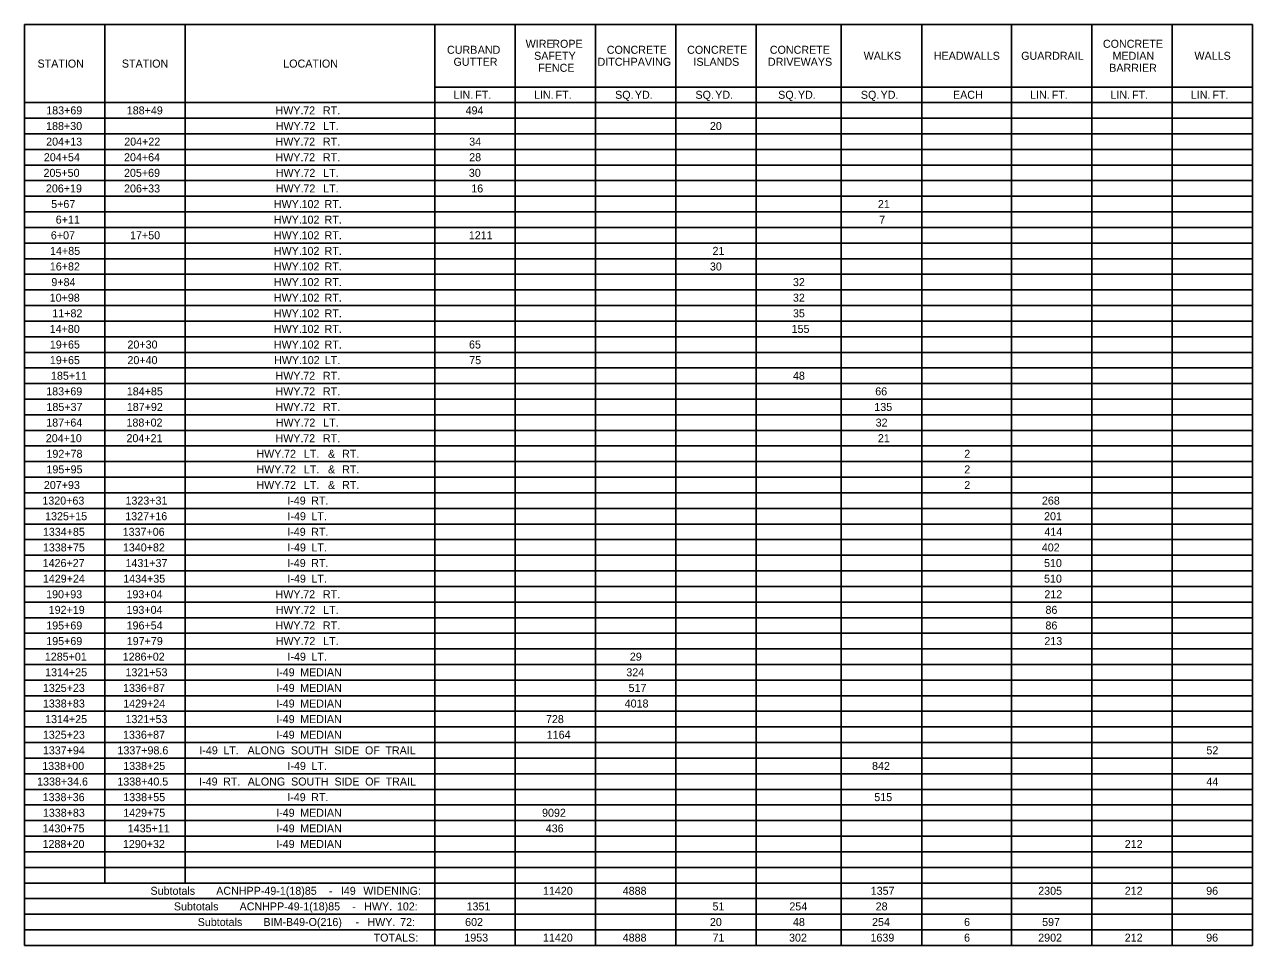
# Model space of a CAD drawing. Extents: x 1226657 to 1228145, y 151309 to 152305.
# Drawn here: x 1226657 to 1227424, y 151359 to 151934 of the extents above; entities that cross this region are included whole.
import ezdxf

# ---------------------------------------------------------------- set-up
doc = ezdxf.new("R2010")
doc.units = 0
doc.layers.add('R_Dimension', color=7, linetype='Continuous')

msp = doc.modelspace()

# ---------------------------------------------------------------- linework, layer by layer
at = {"layer": 'R_Dimension'}
for p, q in [((1226656.54, 151934.12), (1227423.86, 151934.12)), ((1226656.54, 151358.87), (1226656.54, 151934.12)), ((1226706.75, 151397.87), (1226706.75, 151934.12)), ((1226756.96, 151397.87), (1226756.96, 151934.12)), ((1226912.96, 151358.87), (1226912.96, 151934.12)), ((1226963.18, 151358.87), (1226963.18, 151934.12)), ((1227013.39, 151358.87), (1227013.39, 151934.12)), ((1227063.6, 151358.87), (1227063.6, 151934.12)), ((1227113.81, 151358.87), (1227113.81, 151934.12)), ((1227166.95, 151358.87), (1227166.95, 151934.12)), ((1227217.16, 151358.87), (1227217.16, 151934.12)), ((1227273.23, 151358.87), (1227273.23, 151934.12)), ((1227323.44, 151358.87), (1227323.44, 151934.12)), ((1227373.65, 151358.87), (1227373.65, 151934.12)), ((1227423.86, 151358.87), (1227423.86, 151934.12)), ((1226912.96, 151895.12), (1227423.86, 151895.12)), ((1226656.54, 151885.37), (1227423.86, 151885.37)), ((1226656.54, 151875.62), (1227423.86, 151875.62)), ((1226656.54, 151865.87), (1227423.86, 151865.87)), ((1226656.54, 151856.12), (1227423.86, 151856.12)), ((1226656.54, 151846.37), (1227423.86, 151846.37)), ((1226656.54, 151836.62), (1227423.86, 151836.62)), ((1226656.54, 151826.87), (1227423.86, 151826.87)), ((1226656.54, 151817.12), (1227423.86, 151817.12)), ((1226656.54, 151807.37), (1227423.86, 151807.37)), ((1226656.54, 151797.62), (1227423.86, 151797.62)), ((1226656.54, 151787.87), (1227423.86, 151787.87)), ((1226656.54, 151778.12), (1227423.86, 151778.12)), ((1226656.54, 151768.37), (1227423.86, 151768.37)), ((1226656.54, 151758.62), (1227423.86, 151758.62)), ((1226656.54, 151748.87), (1227423.86, 151748.87)), ((1226656.54, 151739.12), (1227423.86, 151739.12)), ((1226656.54, 151729.37), (1227423.86, 151729.37)), ((1226656.54, 151719.62), (1227423.86, 151719.62)), ((1226656.54, 151709.87), (1227423.86, 151709.87)), ((1226656.54, 151700.12), (1227423.86, 151700.12)), ((1226656.54, 151690.37), (1227423.86, 151690.37)), ((1226656.54, 151680.62), (1227423.86, 151680.62)), ((1226656.54, 151670.87), (1227423.86, 151670.87)), ((1226656.54, 151661.12), (1227423.86, 151661.12)), ((1226656.54, 151651.37), (1227423.86, 151651.37)), ((1226656.54, 151641.62), (1227423.86, 151641.62)), ((1226656.54, 151631.87), (1227423.86, 151631.87)), ((1226656.54, 151622.12), (1227423.86, 151622.12)), ((1226656.54, 151612.37), (1227423.86, 151612.37)), ((1226656.54, 151602.62), (1227423.86, 151602.62)), ((1226656.54, 151592.87), (1227423.86, 151592.87)), ((1226656.54, 151583.12), (1227423.86, 151583.12)), ((1226656.54, 151573.37), (1227423.86, 151573.37)), ((1226656.54, 151563.62), (1227423.86, 151563.62)), ((1226656.54, 151553.87), (1227423.86, 151553.87)), ((1226656.54, 151544.12), (1227423.86, 151544.12)), ((1226656.54, 151534.37), (1227423.86, 151534.37)), ((1226656.54, 151524.62), (1227423.86, 151524.62)), ((1226656.54, 151514.87), (1227423.86, 151514.87)), ((1226656.54, 151505.12), (1227423.86, 151505.12)), ((1226656.54, 151495.37), (1227423.86, 151495.37)), ((1226656.54, 151485.62), (1227423.86, 151485.62)), ((1226656.54, 151475.87), (1227423.86, 151475.87)), ((1226656.54, 151466.12), (1227423.86, 151466.12)), ((1226656.54, 151456.37), (1227423.86, 151456.37)), ((1226656.54, 151446.62), (1227423.86, 151446.62)), ((1226656.54, 151436.87), (1227423.86, 151436.87)), ((1226656.54, 151427.12), (1227423.86, 151427.12)), ((1226656.54, 151417.37), (1227423.86, 151417.37)), ((1226656.54, 151407.62), (1227423.86, 151407.62)), ((1226656.54, 151397.87), (1227423.86, 151397.87)), ((1226656.54, 151388.12), (1227423.86, 151388.12)), ((1226656.54, 151378.37), (1227423.86, 151378.37)), ((1226656.54, 151368.62), (1227423.86, 151368.62)), ((1226656.54, 151358.87), (1227423.86, 151358.87))]:
    msp.add_line(p, q, dxfattribs=at)

# ---------------------------------------------------------------- texts
for s, p in [('WIRE', (1226969.68, 151919.62)), (' ROPE', (1226984.48, 151919.62)), ('CONCRETE', (1227330.43, 151919.62)), ('CURB', (1226920.53, 151915.87)), (' AND', (1226937.89, 151915.87)), ('SAFETY', (1226974.97, 151912.12)), ('CONCRETE', (1227020.38, 151915.87)), ('CONCRETE', (1227070.6, 151915.87)), ('CONCRETE', (1227122.27, 151915.87)), ('WALKS', (1227180.92, 151912.12)), ('HEADWALLS', (1227224.76, 151912.12)), ('GUARDRAIL', (1227279.36, 151912.12)), ('MEDIAN', (1227336.44, 151912.12)), ('WALLS', (1227387.62, 151912.12)), ('STATION', (1226664.64, 151907.25)), ('STATION', (1226717.35, 151907.25)), ('LOCATION', (1226818.21, 151907.25)), ('GUTTER', (1226924.62, 151908.37)), ('FENCE', (1226977.53, 151904.62)), ('DITCH', (1227014.6, 151908.37)), (' PAVING', (1227033.42, 151908.37)), ('ISLANDS', (1227074.57, 151908.37)), ('DRIVEWAYS', (1227121.09, 151908.37)), ('BARRIER', (1227334.39, 151904.62)), ('LIN.', (1226924.66, 151887.75)), (' FT.', (1226936.32, 151887.75)), ('LIN.', (1226974.88, 151887.75)), (' FT.', (1226986.53, 151887.75)), ('SQ.', (1227025.6, 151887.75)), (' YD.', (1227036.07, 151887.75)), ('SQ.', (1227075.81, 151887.75)), (' YD.', (1227086.29, 151887.75)), ('SQ.', (1227127.49, 151887.75)), (' YD.', (1227137.96, 151887.75)), ('SQ.', (1227179.16, 151887.75)), (' YD.', (1227189.64, 151887.75)), ('EACH', (1227236.73, 151887.75)), ('LIN.', (1227284.93, 151887.75)), (' FT.', (1227296.58, 151887.75)), ('LIN.', (1227335.14, 151887.75)), (' FT.', (1227346.79, 151887.75)), ('LIN.', (1227385.35, 151887.75)), (' FT.', (1227397, 151887.75)), ('183+69', (1226670.09, 151878)), ('188+49', (1226720.42, 151878)), ('HWY.', (1226813.39, 151878)), (' 72', (1226828.82, 151878)), (' RT.', (1226841.14, 151878)), ('494', (1226932.16, 151878)), ('188+30', (1226670.01, 151868.25)), ('HWY.', (1226813.51, 151868.25)), (' 72', (1226828.94, 151868.25)), (' LT.', (1226841.26, 151868.25)), ('20', (1227084.83, 151868.25)), ('204+13', (1226670.03, 151858.5)), ('204+22', (1226718.83, 151858.5)), ('HWY.', (1226813.39, 151858.5)), (' 72', (1226828.82, 151858.5)), (' RT.', (1226841.14, 151858.5)), ('34', (1226934.41, 151858.5)), ('204+54', (1226668.61, 151848.75)), ('204+64', (1226718.71, 151848.75)), ('HWY.', (1226813.39, 151848.75)), (' 72', (1226828.82, 151848.75)), (' RT.', (1226841.14, 151848.75)), ('28', (1226934.41, 151848.75)), ('205+50', (1226668.4, 151839)), ('205+69', (1226718.69, 151839)), ('HWY.', (1226813.51, 151839)), (' 72', (1226828.94, 151839)), (' LT.', (1226841.26, 151839)), ('30', (1226934.19, 151839)), ('206+19', (1226669.89, 151829.25)), ('206+33', (1226718.71, 151829.25)), ('HWY.', (1226813.51, 151829.25)), (' 72', (1226828.94, 151829.25)), (' LT.', (1226841.26, 151829.25)), ('16', (1226935.69, 151829.25)), ('5+67', (1226673.18, 151819.5)), ('HWY.', (1226812.36, 151819.5)), (' 102', (1226827.8, 151819.5)), (' RT.', (1226842.17, 151819.5)), ('21', (1227189.81, 151819.5)), ('6+11', (1226676.01, 151809.75)), ('HWY.', (1226812.36, 151809.75)), (' 102', (1226827.8, 151809.75)), (' RT.', (1226842.17, 151809.75)), ('7', (1227190.64, 151809.75)), ('6+07', (1226672.98, 151800)), ('17+50', (1226722.47, 151800)), ('HWY.', (1226812.36, 151800)), (' 102', (1226827.8, 151800)), (' RT.', (1226842.17, 151800)), ('1211', (1226934.17, 151800)), ('14+85', (1226672.47, 151790.25)), ('HWY.', (1226812.36, 151790.25)), (' 102', (1226827.8, 151790.25)), (' RT.', (1226842.17, 151790.25)), ('21', (1227086.46, 151790.25)), ('16+82', (1226672.35, 151780.5)), ('HWY.', (1226812.36, 151780.5)), (' 102', (1226827.8, 151780.5)), (' RT.', (1226842.17, 151780.5)), ('30', (1227084.83, 151780.5)), ('9+84', (1226673.3, 151770.75)), ('HWY.', (1226812.36, 151770.75)), (' 102', (1226827.8, 151770.75)), (' RT.', (1226842.17, 151770.75)), ('32', (1227136.72, 151770.75)), ('10+98', (1226672.27, 151761)), ('HWY.', (1226812.36, 151761)), (' 102', (1226827.8, 151761)), (' RT.', (1226842.17, 151761)), ('32', (1227136.72, 151761)), ('11+82', (1226673.89, 151751.25)), ('HWY.', (1226812.36, 151751.25)), (' 102', (1226827.8, 151751.25)), (' RT.', (1226842.17, 151751.25)), ('35', (1227136.72, 151751.25)), ('14+80', (1226672.25, 151741.5)), ('HWY.', (1226812.36, 151741.5)), (' 102', (1226827.8, 151741.5)), (' RT.', (1226842.17, 151741.5)), ('155', (1227135.89, 151741.5)), ('19+65', (1226672.35, 151731.75)), ('20+30', (1226720.85, 151731.75)), ('HWY.', (1226812.36, 151731.75)), (' 102', (1226827.8, 151731.75)), (' RT.', (1226842.17, 151731.75)), ('65', (1226934.29, 151731.75)), ('19+65', (1226672.35, 151722)), ('20+40', (1226720.85, 151722)), ('HWY.', (1226812.48, 151722)), (' 102', (1226827.92, 151722)), (' LT.', (1226842.29, 151722)), ('75', (1226934.41, 151722)), ('185+11', (1226673.06, 151712.25)), ('HWY.', (1226813.39, 151712.25)), (' 72', (1226828.82, 151712.25)), (' RT.', (1226841.14, 151712.25)), ('48', (1227136.72, 151712.25)), ('183+69', (1226670.09, 151702.5)), ('184+85', (1226720.44, 151702.5)), ('HWY.', (1226813.39, 151702.5)), (' 72', (1226828.82, 151702.5)), (' RT.', (1226841.14, 151702.5)), ('66', (1227188.14, 151702.5)), ('185+37', (1226670.23, 151692.75)), ('187+92', (1226720.44, 151692.75)), ('HWY.', (1226813.39, 151692.75)), (' 72', (1226828.82, 151692.75)), (' RT.', (1226841.14, 151692.75)), ('135', (1227187.57, 151692.75)), ('187+64', (1226670.11, 151683)), ('188+02', (1226720.24, 151683)), ('HWY.', (1226813.51, 151683)), (' 72', (1226828.94, 151683)), (' LT.', (1226841.26, 151683)), ('32', (1227188.4, 151683)), ('204+10', (1226669.81, 151673.25)), ('204+21', (1226720.24, 151673.25)), ('HWY.', (1226813.39, 151673.25)), (' 72', (1226828.82, 151673.25)), (' RT.', (1226841.14, 151673.25)), ('21', (1227189.81, 151673.25)), ('192+78', (1226670.23, 151663.5)), ('HWY.', (1226801.42, 151663.5)), (' 72', (1226816.85, 151663.5)), (' LT.', (1226829.18, 151663.5)), (' &', (1226844.33, 151663.5)), (' RT.', (1226853.11, 151663.5)), ('2', (1227243.78, 151663.5)), ('195+95', (1226670.23, 151653.75)), ('HWY.', (1226801.42, 151653.75)), (' 72', (1226816.85, 151653.75)), (' LT.', (1226829.18, 151653.75)), (' &', (1226844.33, 151653.75)), (' RT.', (1226853.11, 151653.75)), ('2', (1227243.78, 151653.75)), ('207+93', (1226668.61, 151644)), ('HWY.', (1226801.42, 151644)), (' 72', (1226816.85, 151644)), (' LT.', (1226829.18, 151644)), (' &', (1226844.33, 151644)), (' RT.', (1226853.11, 151644)), ('2', (1227243.78, 151644)), ('1320+63', (1226667.67, 151634.25)), ('1323+31', (1226719.61, 151634.25)), ('I-49', (1226820.71, 151634.25)), (' RT.', (1226833.82, 151634.25)), ('268', (1227292.31, 151634.25)), ('1325+15', (1226669.4, 151624.5)), ('1327+16', (1226719.47, 151624.5)), ('I-49', (1226820.83, 151624.5)), (' LT.', (1226833.94, 151624.5)), ('201', (1227293.65, 151624.5)), ('1334+85', (1226667.98, 151614.75)), ('1337+06', (1226717.86, 151614.75)), ('I-49', (1226820.71, 151614.75)), (' RT.', (1226833.82, 151614.75)), ('414', (1227293.84, 151614.75)), ('1338+75', (1226667.98, 151605)), ('1340+82', (1226718, 151605)), ('I-49', (1226820.83, 151605)), (' LT.', (1226833.94, 151605)), ('402', (1227292.23, 151605)), ('1426+27', (1226667.86, 151595.25)), ('1431+37', (1226719.61, 151595.25)), ('I-49', (1226820.71, 151595.25)), (' RT.', (1226833.82, 151595.25)), ('510', (1227293.63, 151595.25)), ('1429+24', (1226667.98, 151585.5)), ('1434+35', (1226718.2, 151585.5)), ('I-49', (1226820.83, 151585.5)), (' LT.', (1226833.94, 151585.5)), ('510', (1227293.63, 151585.5)), ('190+93', (1226670.03, 151575.75)), ('193+04', (1226720.24, 151575.75)), ('HWY.', (1226813.39, 151575.75)), (' 72', (1226828.82, 151575.75)), (' RT.', (1226841.14, 151575.75)), ('212', (1227293.84, 151575.75)), ('192+19', (1226671.62, 151566)), ('193+04', (1226720.24, 151566)), ('HWY.', (1226813.51, 151566)), (' 72', (1226828.94, 151566)), (' LT.', (1226841.26, 151566)), ('86', (1227294.53, 151566)), ('195+69', (1226670.09, 151556.25)), ('196+54', (1226720.32, 151556.25)), ('HWY.', (1226813.39, 151556.25)), (' 72', (1226828.82, 151556.25)), (' RT.', (1226841.14, 151556.25)), ('86', (1227294.53, 151556.25)), ('195+69', (1226670.09, 151546.5)), ('197+79', (1226720.42, 151546.5)), ('HWY.', (1226813.51, 151546.5)), (' 72', (1226828.94, 151546.5)), (' LT.', (1226841.26, 151546.5)), ('213', (1227293.84, 151546.5)), ('1285+01', (1226669.2, 151536.75)), ('1286+02', (1226717.88, 151536.75)), ('I-49', (1226820.83, 151536.75)), (' LT.', (1226833.94, 151536.75)), ('29', (1227034.81, 151536.75)), ('1314+25', (1226669.4, 151527)), ('1321+53', (1226719.61, 151527)), ('I-49', (1226813.8, 151527)), (' MEDIAN', (1226826.91, 151527)), ('324', (1227032.59, 151527)), ('1325+23', (1226667.98, 151517.25)), ('1336+87', (1226718.08, 151517.25)), ('I-49', (1226813.8, 151517.25)), (' MEDIAN', (1226826.91, 151517.25)), ('517', (1227034.01, 151517.25)), ('1338+83', (1226667.98, 151507.5)), ('1429+24', (1226718.2, 151507.5)), ('I-49', (1226813.8, 151507.5)), (' MEDIAN', (1226826.91, 151507.5)), ('4018', (1227031.57, 151507.5)), ('1314+25', (1226669.4, 151497.75)), ('1321+53', (1226719.61, 151497.75)), ('I-49', (1226813.8, 151497.75)), (' MEDIAN', (1226826.91, 151497.75)), ('728', (1226982.38, 151497.75)), ('1325+23', (1226667.98, 151488)), ('1336+87', (1226718.08, 151488)), ('I-49', (1226813.8, 151488)), (' MEDIAN', (1226826.91, 151488)), ('1164', (1226982.85, 151488)), ('1337+94', (1226667.98, 151478.25)), ('1337+98.6', (1226714.59, 151478.25)), ('I-49', (1226765.77, 151478.25)), (' LT.', (1226778.88, 151478.25)), (' ALONG', (1226794.04, 151478.25)), (' SOUTH', (1226821.12, 151478.25)), (' SIDE', (1226848.25, 151478.25)), (' OF', (1226867.42, 151478.25)), (' TRAIL', (1226880.18, 151478.25)), ('52', (1227395.1, 151478.25)), ('1338+00', (1226667.57, 151468.5)), ('1338+25', (1226718.2, 151468.5)), ('I-49', (1226820.83, 151468.5)), (' LT.', (1226833.94, 151468.5)), ('842', (1227186.15, 151468.5)), ('1338+34.6', (1226664.38, 151458.75)), ('1338+40.5', (1226714.53, 151458.75)), ('I-49', (1226765.65, 151458.75)), (' RT.', (1226778.76, 151458.75)), (' ALONG', (1226794.16, 151458.75)), (' SOUTH', (1226821.24, 151458.75)), (' SIDE', (1226848.37, 151458.75)), (' OF', (1226867.54, 151458.75)), (' TRAIL', (1226880.3, 151458.75)), ('44', (1227395.1, 151458.75)), ('1338+36', (1226667.85, 151449)), ('1338+55', (1226718.2, 151449)), ('I-49', (1226820.71, 151449)), (' RT.', (1226833.82, 151449)), ('515', (1227187.57, 151449)), ('1338+83', (1226667.98, 151439.25)), ('1429+75', (1226718.2, 151439.25)), ('I-49', (1226813.8, 151439.25)), (' MEDIAN', (1226826.91, 151439.25)), ('9092', (1226979.94, 151439.25)), ('1430+75', (1226667.79, 151429.5)), ('1435+11', (1226721.03, 151429.5)), ('I-49', (1226813.8, 151429.5)), (' MEDIAN', (1226826.91, 151429.5)), ('436', (1226982.24, 151429.5)), ('1288+20', (1226667.77, 151419.75)), ('1290+32', (1226718, 151419.75)), ('I-49', (1226813.8, 151419.75)), (' MEDIAN', (1226826.91, 151419.75)), ('212', (1227344.06, 151419.75)), ('Subtotals', (1226735.25, 151390.5)), (' ACNHPP-49-1(18)85', (1226774.46, 151390.5)), (' I49', (1226852.34, 151390.5)), (' WIDENING:', (1226866.35, 151390.5)), ('11420', (1226980.51, 151390.5)), ('4888', (1227030.34, 151390.5)), ('1357', (1227185.32, 151390.5)), ('2305', (1227289.99, 151390.5)), ('212', (1227344.06, 151390.5)), ('96', (1227394.96, 151390.5)), ('Subtotals', (1226749.86, 151380.75)), (' ACNHPP-49-1(18)85', (1226789.07, 151380.75)), (' -', (1226844.9, 151390.5)), (' HWY.', (1226866.94, 151380.75)), (' 102:', (1226887.38, 151380.75)), ('1351', (1226932.75, 151380.75)), ('51', (1227086.46, 151380.75)), ('254', (1227134.48, 151380.75)), ('28', (1227188.4, 151380.75)), (' -', (1226859.5, 151380.75)), ('Subtotals', (1226764.74, 151371)), (' BIM-B49-O(216)', (1226803.95, 151371)), (' -', (1226861.55, 151371)), (' HWY.', (1226868.99, 151371)), (' 72:', (1226889.42, 151371)), ('602', (1226931.85, 151371)), ('20', (1227084.83, 151371)), ('48', (1227136.72, 151371)), ('254', (1227186.15, 151371)), ('6', (1227243.64, 151371)), ('597', (1227292.43, 151371)), ('TOTALS:', (1226874.66, 151361.25)), ('1953', (1226931.34, 151361.25)), ('11420', (1226980.51, 151361.25)), ('4888', (1227030.34, 151361.25)), ('71', (1227086.46, 151361.25)), ('302', (1227134.28, 151361.25)), ('1639', (1227185.19, 151361.25)), ('6', (1227243.64, 151361.25)), ('2902', (1227289.99, 151361.25)), ('212', (1227344.06, 151361.25)), ('96', (1227394.96, 151361.25))]:
    msp.add_text(s, height=5, dxfattribs=at).set_placement(p)

doc.saveas('drawing.dxf')
